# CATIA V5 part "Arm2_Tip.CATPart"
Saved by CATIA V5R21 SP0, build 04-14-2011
Part number: Arm2_Tip
Bounding box of the stored display mesh (mm): x 0 to 13, y -12.5 to 12.5, z -12.5 to 12.5
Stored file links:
  F:\教程\Robotic_Arm_Arduino_Kinect\机械臂CAD\Arm_Detailed_Design\Arm2_Tip.CATPart
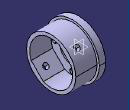
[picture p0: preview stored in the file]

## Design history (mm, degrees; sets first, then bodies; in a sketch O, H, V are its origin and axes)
Body1 (main body)
  Sketch1 on yz-plane, origin (0, 0, 0), H (0, 1, 0), V (0, 0, 1)
    circle A1 centre (0, 0) radius 12.5
    circle A2 centre (0, 8.5) radius 1.25
    point P1 (0, 8.5)
    circle A3 centre (-8.5, 0) radius 1.25
    circle A4 centre (0, -8.5) radius 1.25
    circle A5 centre (8.5, 0) radius 1.25
    circle A6 centre (0, 0) radius 6
    radius A1 = 12.5
    radius A2 = 1.25
    distance H P1 = 8.5
    radius A6 = 6
    coincidence: P1 V
  Pad1: profile Sketch1, direction (1, 0, 0), length 3
  Sketch2 on end face of Pad1, origin (3, 0, 0), H (0, 1, 0), V (0, 0, 1)
    circle A1 centre (0, 0) radius 11.5
    arc A2 centre (0, 0) radius 10 from (3.6523, 9.3092) to (-9.3092, -3.6523) ccw
    line L1 (3.6523, 9.3092) -> (9.3092, 3.6523)
    line L2 (-9.3092, -3.6523) -> (-3.6523, -9.3092)
    point P4 (-3.6523, -9.3092)
    arc A3 centre (0, 0) radius 10 from (-3.6523, -9.3092) to (9.3092, 3.6523) ccw
    radius A1 = 11.5
    radius A2 = 10
    coincidence: P4 A2, A2 A3
  Pad2: profile Sketch2, direction (1, 0, 0), length 10
  Sketch3 on face of Pad2 from Sketch2.L2, origin (0, -6.4807, -6.4807), H (-1, 0, 0), V (0, -0.7071, 0.7071)
    circle A1 centre (-9, 0) radius 1.25
    point P1 (-9, 0)
    point P2 (-7.75, 0)
    reference projected line E1 (-3, 4) -> (-3, -4) from edge [face of Pad2 from Sketch2.L2 | end face of Pad1]
    radius A1 = 1.25
    distance E1 P1 = 6
    coincidence: P1 H, A1 P2, P2 H
  Pocket1: profile Sketch3, direction (0, -0.7071, -0.7071), through (limit type 3)
  Sketch4 on face of Pad2 from Sketch2.L1, origin (0, 6.4807, 6.4807), H (1, 0, 0), V (0, -0.7071, 0.7071)
    circle A1 centre (9, 0) radius 1.25
    point P1 (9, 0)
    reference projected line E1 (3, -4) -> (3, 4) from edge [face of Pad2 from Sketch2.L1 | end face of Pad1]
    radius A1 = 1.25
    distance P1 E1 = 6
    coincidence: P1 H
  Pocket2: profile Sketch4, direction (0, 0.7071, 0.7071), through (limit type 3)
